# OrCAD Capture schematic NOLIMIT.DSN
size A
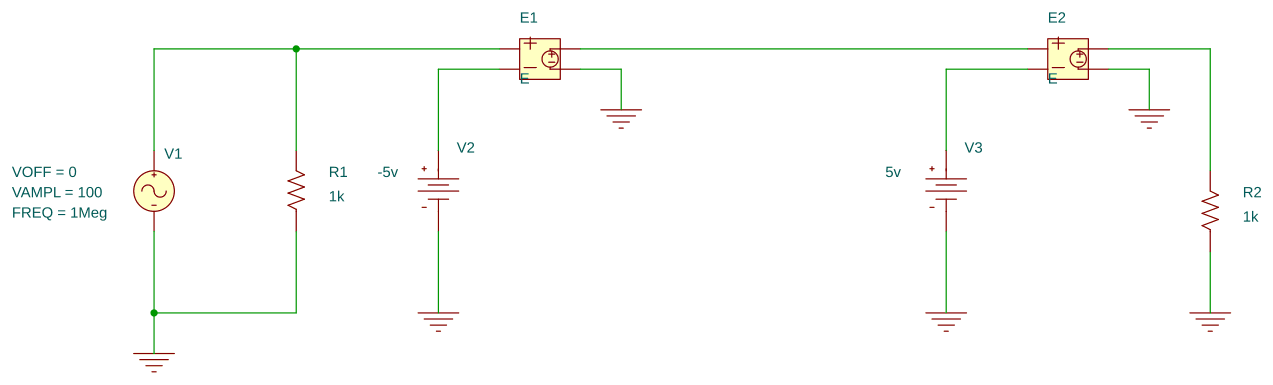
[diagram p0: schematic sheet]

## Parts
E1  E
E2  E
R1  1k  [AX/RC05]
R2  1k  [AX/RC05]
V1  VSIN
V2  VDC
V3  VDC

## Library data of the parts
E1 E2 = E: GAIN: 1e6
R1 R2 = R
V1 = VSIN: FREQ: 1Meg; VAMPL: 100; VOFF: 0
V2 = VDC: DC: -5v
V3 = VDC: DC: 5v

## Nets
0: E1.4 E2.4 R1.1 R2.1 V1.2(-) V2.1(-) V3.1(-)
N00201: E1.1 R1.2 V1.1(+)
N00246: E1.2 V2.0(+)
N00290: E1.3 E2.1
N00306: E2.2 V3.0(+)
N00345: E2.3 R2.2
